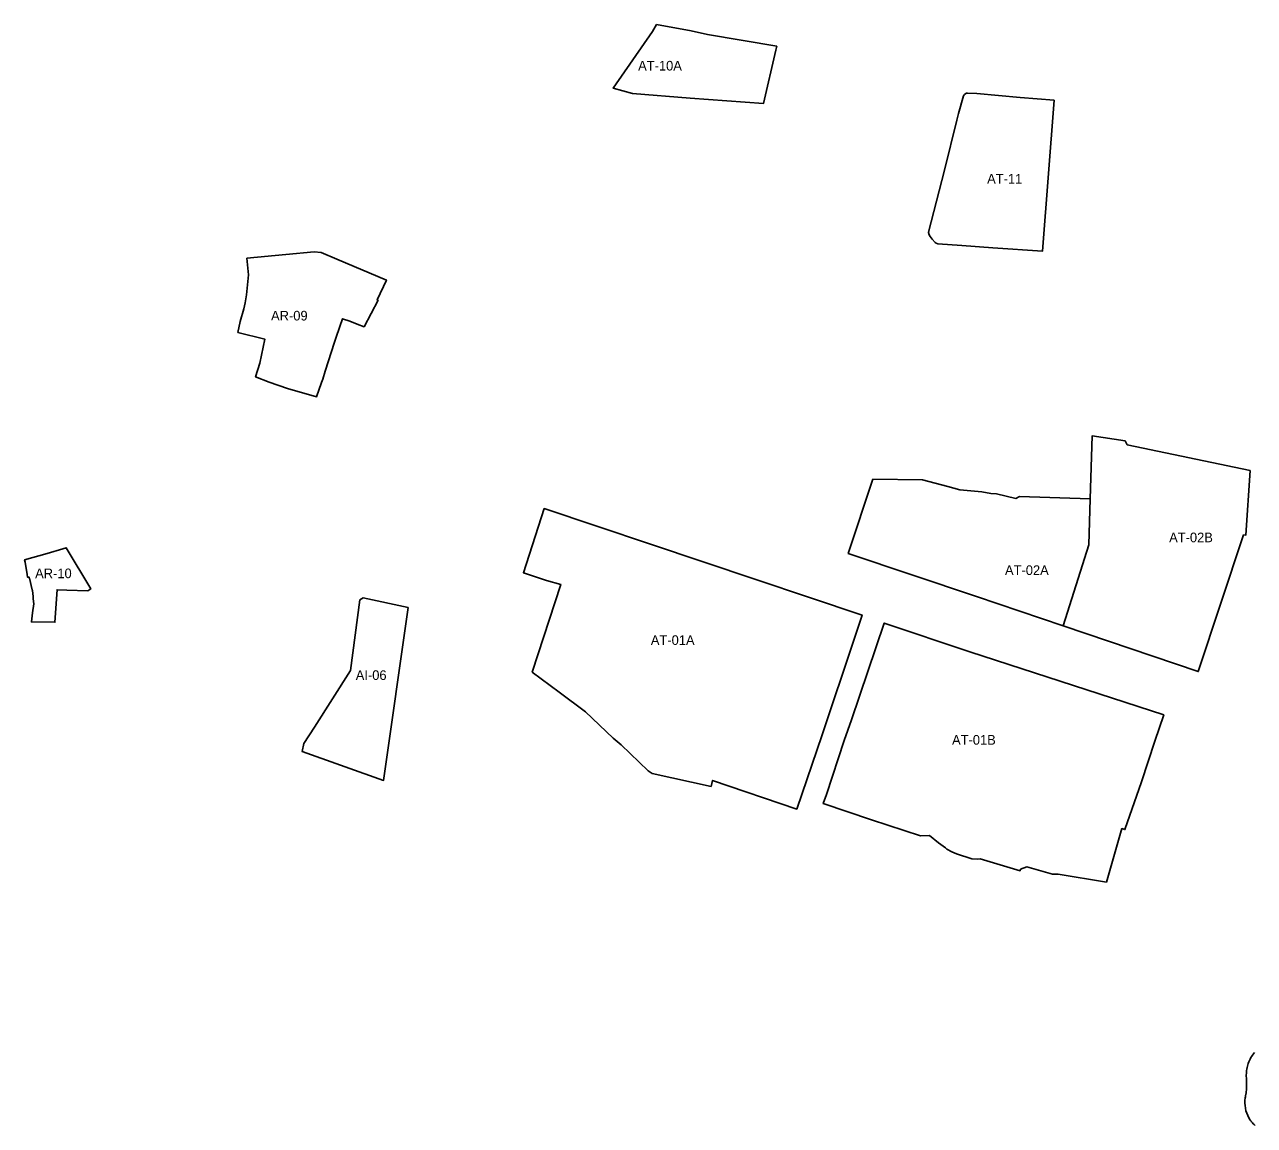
# Model space of a CAD drawing. Extents: x 428342 to 437063, y 4455780 to 4463043.
# Drawn here: x 432857 to 433494, y 4458945 to 4459515 of the extents above; entities that cross this region are included whole.
import ezdxf

# ---------------------------------------------------------------- set-up
doc = ezdxf.new("R2010")
doc.units = 0
for name, color, linetype in [('AMB_SUNC-Residenciales', 7, 'Continuous'), ('AMB_SUNC-Txt', 7, 'Continuous'), ('AMB_SUS-Empresarial', 7, 'Continuous')]:
    doc.layers.add(name, color=color, linetype=linetype)

msp = doc.modelspace()

# ---------------------------------------------------------------- linework, layer by layer
at = {"layer": 'AMB_SUNC-Residenciales'}
for points in [[(433172.26, 4459479.36), (433202.07, 4459477.06), (433240.15, 4459474.32), (433246.49, 4459501.89), (433246.95, 4459503.88), (433210.99, 4459510.08), (433202.63, 4459511.83), (433184.67, 4459515.13), (433182.55, 4459511.5), (433162.23, 4459482.16), (433172.26, 4459479.36)], [(433342.82, 4459400.68), (433358.98, 4459399.47), (433384.7, 4459397.76), (433390.69, 4459475.92), (433373.12, 4459477.34), (433350.71, 4459479.35), (433345.79, 4459479.69), (433345.25, 4459479.53), (433345, 4459479.42), (433344.31, 4459478.95), (433343.77, 4459478.31), (433341.15, 4459469.08), (433340.3, 4459465.63), (433333.93, 4459439.68), (433325.63, 4459407.63), (433325.63, 4459407.34), (433325.87, 4459406.25), (433326.43, 4459405.27), (433327.47, 4459403.92), (433329.06, 4459402.32), (433329.53, 4459401.96), (433330.44, 4459401.6), (433342.82, 4459400.68)], [(432992.46, 4459395.97), (432972.37, 4459394.06), (432973.11, 4459385.56), (432972.23, 4459375.19), (432971.39, 4459371.01), (432970.7, 4459367.88), (432968.86, 4459361.32), (432967.66, 4459355.64), (432981.65, 4459352.1), (432979.1, 4459339.7), (432976.87, 4459332.57), (432983.95, 4459329.95), (432993.39, 4459326.57), (433008.44, 4459322.3), (433010.93, 4459329.79), (433011.71, 4459331.51), (433012.87, 4459335.59), (433014.61, 4459340.86), (433017.63, 4459350.02), (433018.52, 4459352.69), (433020.53, 4459358.74), (433021.91, 4459362.73), (433025.73, 4459361.45), (433029.48, 4459360), (433033.06, 4459358.63), (433040.34, 4459372.3), (433039.87, 4459372.5), (433044.68, 4459382.8), (433018.98, 4459393.62), (433010.9, 4459397.02), (433007.28, 4459397.36), (432992.46, 4459395.97)], [(433409.34, 4459269.45), (433408.62, 4459245.63), (433395.38, 4459203.67), (433465.37, 4459179.92), (433488.87, 4459250.75), (433490.06, 4459250.65), (433492.23, 4459284.09), (433428.55, 4459297.49), (433427.47, 4459299.52), (433410.33, 4459302.02), (433409.34, 4459269.45)], [(433395.38, 4459203.67), (433408.62, 4459245.63), (433409.34, 4459269.45), (433372.77, 4459270.64), (433370.89, 4459269.7), (433360.86, 4459271.97), (433357.95, 4459272.25), (433353.18, 4459273.08), (433341.81, 4459274.19), (433335.62, 4459275.75), (433322.48, 4459279.2), (433296.79, 4459279.56), (433283.96, 4459241.15), (433350.43, 4459218.92), (433395.38, 4459203.67)], [(433270.4, 4459147.25), (433274.24, 4459158.62), (433283.3, 4459185.37), (433291.12, 4459209.19), (433126.46, 4459264.4), (433115.66, 4459231.14), (433127.63, 4459227.2), (433135.01, 4459225.08), (433120.25, 4459179.7), (433134.25, 4459169.24), (433147.78, 4459159.05), (433162.09, 4459145.48), (433166.33, 4459141.95), (433180.22, 4459128.6), (433182.46, 4459127.07), (433212.94, 4459120.47), (433213.65, 4459123.52), (433257.29, 4459108.7), (433270.4, 4459147.25)], [(432861.33, 4459210.45), (432860.65, 4459205.69), (432872.86, 4459205.47), (432873.95, 4459222.33), (432879.05, 4459222.1), (432889.92, 4459221.81), (432891.43, 4459222.76), (432878.74, 4459244.1), (432877.01, 4459243.58), (432868.88, 4459241.13), (432857.15, 4459237.86), (432857.36, 4459236.68), (432858.47, 4459230.29), (432858.66, 4459228.81), (432859.44, 4459228.92), (432859.53, 4459228.28), (432859.68, 4459228.3), (432861.09, 4459222.38), (432861.2, 4459221.91), (432861.52, 4459218.84), (432861.64, 4459217.71), (432861.91, 4459215.05), (432861.33, 4459210.45)], [(433032.54, 4459218.13), (433030.84, 4459217.07), (433026, 4459180.54), (433007.44, 4459151.16), (433001.92, 4459142.63), (433000.93, 4459138.62), (433043.19, 4459123.53), (433055.87, 4459213.07), (433032.54, 4459218.13)], [(433285.64, 4459154.89), (433281.89, 4459144.23), (433272.65, 4459116.33), (433271.02, 4459111.59), (433295.97, 4459103.07), (433321.35, 4459094.77), (433326.08, 4459095.11), (433330.78, 4459091.18), (433334.42, 4459088.55), (433335.13, 4459088.03), (433337.63, 4459086.6), (433340.07, 4459085.47), (433348.09, 4459083.02), (433351.09, 4459082.76), (433352.4, 4459082.99), (433373.1, 4459076.79), (433373.31, 4459077.5), (433376.56, 4459078.84), (433389.77, 4459074.94), (433392.79, 4459075.06), (433417.82, 4459070.9), (433425.82, 4459098.6), (433427.4, 4459098.12), (433435.91, 4459122.88), (433442.93, 4459143.89), (433447.53, 4459157.47), (433347.03, 4459190.13), (433302.62, 4459205.04), (433285.64, 4459154.89)]]:
    msp.add_lwpolyline(points, dxfattribs=at)
at = {"layer": 'AMB_SUS-Empresarial'}
msp.add_lwpolyline([(433494.57, 4458982.54), (433494.03, 4458981.93), (433493.53, 4458981.29), (433493.06, 4458980.62), (433492.63, 4458979.93), (433492.24, 4458979.22), (433491.88, 4458978.49), (433491.57, 4458977.75), (433491.29, 4458976.99), (433491.06, 4458976.26), (433490.85, 4458975.52), (433490.68, 4458974.77), (433490.54, 4458974.02), (433490.43, 4458973.27), (433490.35, 4458972.51), (433490.3, 4458971.75), (433490.28, 4458970.99), (433490.29, 4458970.23), (433490.34, 4458969.48), (433490.39, 4458968.75), (433490.45, 4458966.61), (433490.44, 4458966.01), (433490.35, 4458963.83), (433490.12, 4458961.64), (433489.87, 4458960.11), (433489.8, 4458959.69), (433489.69, 4458959.05), (433489.56, 4458957.72), (433489.53, 4458956.39), (433489.61, 4458955.06), (433489.8, 4458953.74), (433490.11, 4458952.44), (433490.52, 4458951.17), (433491.03, 4458949.94), (433491.64, 4458948.76), (433492.35, 4458947.63), (433492.75, 4458947.09), (433493.02, 4458946.73), (433493.49, 4458946.17), (433493.9, 4458945.68), (433494.31, 4458945.28), (433494.81, 4458944.84)], dxfattribs=at)

# ---------------------------------------------------------------- texts
at = {"layer": 'AMB_SUNC-Txt'}
for s, p in [('AT-10A', (433175.11, 4459491.34)), ('AT-11', (433355.97, 4459432.77)), ('AR-09', (432984.87, 4459361.84)), ('AT-02B', (433450.29, 4459246.94)), ('AT-02A', (433365.22, 4459229.99)), ('AR-10', (432862.6, 4459228.33)), ('AT-01A', (433181.69, 4459193.75)), ('AI-06', (433028.76, 4459175.61)), ('AT-01B', (433337.78, 4459142.08))]:
    msp.add_text(s, height=5, dxfattribs=at).set_placement(p)

doc.saveas('drawing.dxf')
